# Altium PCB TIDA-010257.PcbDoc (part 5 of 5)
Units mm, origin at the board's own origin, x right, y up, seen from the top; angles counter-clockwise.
Board outline 250 x 270 mm, 2 copper layers (Top Layer, Bottom Layer), stack 1.575 mm thick; 458 components, 220 nets, 1154 pads, 1226 vias.
Unrouted connection lines stored in the file: 314.
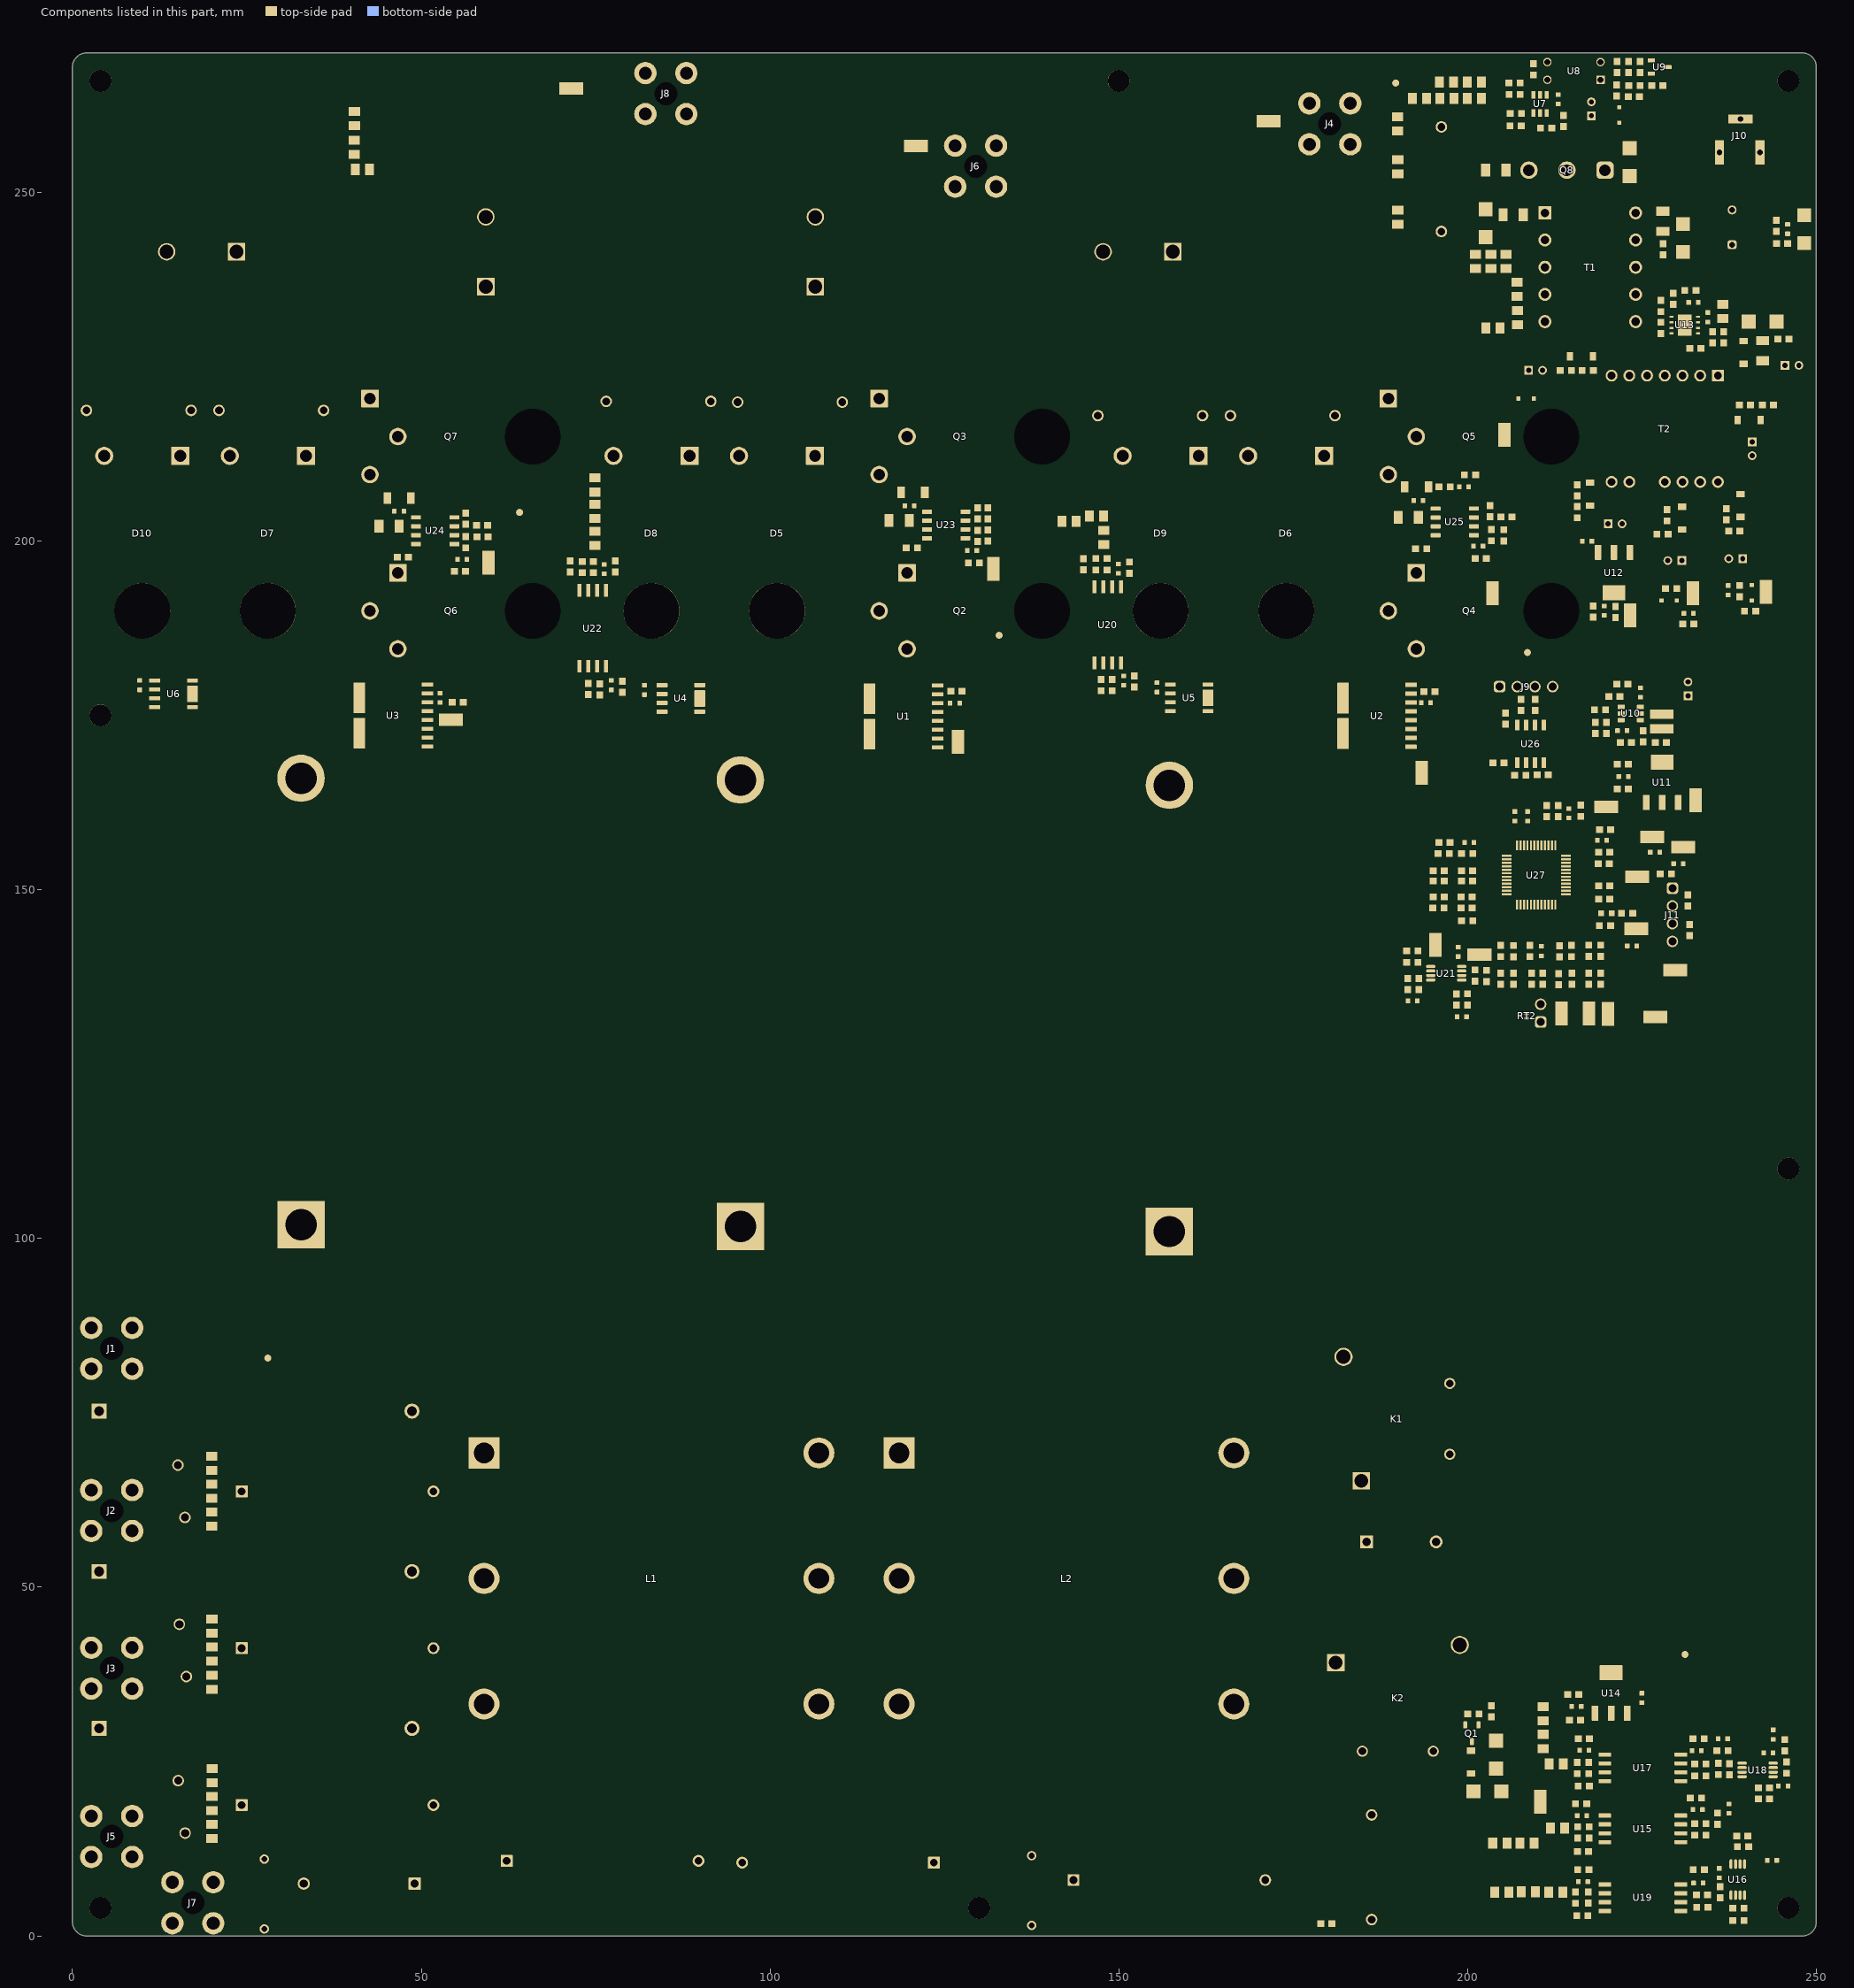
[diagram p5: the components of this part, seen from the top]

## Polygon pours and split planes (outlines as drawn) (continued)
VBUSM on Bottom Layer "BOTTOM_LAYER_VBUSM_P040" (solid, pour order 40): 70,197.842 70,192.467 71.46,191.007 77.247,191.007 77.815,191.575 77.815,193.77 78.75,194.705 78.75,198.826 77.55,200.026 70.737,200.026 70,199.289
GND_ISO on Bottom Layer "BOTTOM_LAYER_GND_ISO_P031" (solid, pour order 31): 202.929,180.586 202.929,173.956 204.069,172.816 212.251,172.816 213.75,174.315 213.75,180.314 212.974,181.09 203.433,181.09
VBUSN on Bottom Layer "BOTTOM_LAYER_VBUSN_P030" (solid, pour order 30): 199.682,34.584 199.353,34.584 192.442,34.584 188.118,30.26 182.885,30.26 182,29.375 182,20.5 183.345,19.155 190.45,19.155 204.833,19.155 205.949,20.271 205.949,33.142 204.831,34.26 204.318,34.26 203.968,34.584
GND_ACSensing on Bottom Layer "BOTTOM_LAYER_GND_ACSENSING_P024" (solid, pour order 24): 19 vertices, not listed, extent 191.25,0.5 227.336,38.883
GND_GATEC on Bottom Layer "Bottom Layer-GND_GATEC" (solid, pour order 6): 24 vertices, not listed, extent 40,182.25 51.145,220.148

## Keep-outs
Top Layer:
  circle w0.254: c4,4 r5
  circle w0.254: c246,4 r5
  circle w0.254: c4,175 r5
  circle w0.254: c246,110 r5
  circle w0.254: c246,266 r5
  circle w0.254: c4,266 r5
  circle w0.254: c150,266 r5
Bottom Layer:
  circle w0.254: c246,266 r3.553
  circle w0.254: c4,266 r3.553
  circle w0.254: c150,266 r3.553
Keep-Out Layer:
  circle w0.254: c246,110 r3.553
  text ".Layer_Name" at 14.656,-21.806 h1.52

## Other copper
Top Layer:
  text ".Layer_Name" at 14.656,-21.806 h1.52
Bottom Layer:
  text ".Layer_Name" at 14.656,-21.806 h1.52

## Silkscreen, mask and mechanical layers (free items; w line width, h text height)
Top Overlay:
  lines w0.2: 237.731,230.559 238.418,231.245 238.418,233.225 ; 203.211,106.245 203.211,107.612 210.177,107.612 210.177,108.612 211.877,106.912 210.177,105.212 210.177,106.245 203.211,106.245
  text "TIDA-010257" at 46.453,267.1 h1.5
  text "20241206" at 25.081,266.6 h1.5
  text "10kW Vienna PFC" at 42.748,264.68 h1.5
  text "VBUSN" at 90.979,264.44 h1.5
  text "VerB" at 27.5,264 h1.5
  text "GND" at 91.9,262 h1.5
  text "VBUSM" at 125.219,261.65 h1.5
  text "MID" at 127.066,259.621 h1.5
  text "VBUSP" at 167.738,256.78 h1.5
  text "Q5" at 193.507,216.906 h1
  text "Q7" at 48.725,214.45 h1
  text "Q3" at 121.98,214.45 h1
  text "15V_B" at 201.762,213.325 h1 r90
  text "D8" at 80.7,210.359 h1
  text "D9" at 153.95,209.756 h1
  text "D5" at 97.861,209.681 h1
  text "D7" at 24.7,209.516 h1
  text "D6" at 170.624,209.382 h1
  text "D10" at 6.706,209.2 h1
  text "PHASE B" at 171.076,202.907 h1.5
  text "PHASE C" at 26.55,202.183 h1.5
  text "PHASE A" at 98.161,201.812 h1.5
  text "PWMC" at 64.145,195.346 h1 r90
  text "PWMA" at 136.135,194.331 h1 r90
  text "PWMB" at 201.965,190.749 h1 r90
  text "15V_C" at 247.033,190.347 h1 r90
  text "15V_A" at 236.068,189.837 h1 r90
  text "Q6" at 39.117,189.467 h1
  text "Q2" at 111.82,189.379 h1
  text "Q4" at 185.026,189.24 h1
  text "3.3V_DC" at 225.846,184.237 h1 r90
  text "IC" at 56.614,173.817 h1
  text "IA" at 124.628,166.1 h1
  text "IB" at 192.425,161.602 h1
  text "5.4V" at 236.9,161.357 h1 r90
  text "3.3V" at 218.41,159.529 h1
  text "DAC0" at 228.378,159.19 h1
  text "DAC1" at 233.09,155.916 h1
  text "IO32" at 214.763,151.452 h1
  text "VP" at 191.069,145.192 h1
  text "VN" at 198.403,142.217 h1
  text "IO33" at 224.684,141.217 h1
  text "GND" at 232.538,138.528 h1
  text "GND" at 229.737,131.77 h1
  text "VB" at 218.477,127.974 h1 r90
  text "VC" at 222.462,127.906 h1 r90
  text "VA" at 214.944,127.774 h1 r90
  text "Soldering" at 200.5,103.7 h1.5
  text "A" at 2.5,90.9 h1.5
  text "10kW Vienna PFC" at 216.374,86.4 h1.5
  text "TIDA-010257" at 218.562,83.5 h1.5
  text "20241206" at 220.5,80.3 h1.5
  text "VerB" at 223.382,77.9 h1.5
  text "B" at 2.13,67.018 h1.5
  text "C" at 1.68,43.675 h1.5
  text "N" at 3.07,19.508 h1.5
  text "3.3V_AC" at 207.152,15.574 h1 r90
  text "E" at 10.2,1.3 h1.5
  text ".Layer_Name" at 14.656,-21.806 h1.52
Bottom Overlay:
  text ".Layer_Name" at 14.656,-21.806 h1.52
Top Paste:
  text ".Layer_Name" at 14.656,-21.806 h1.52
Bottom Paste:
  text ".Layer_Name" at 14.656,-21.806 h1.52
Top Solder:
  text ".Layer_Name" at 14.656,-21.806 h1.52
  text ".Layer_Name" at 14.656,-21.806 h1.52
Bottom Solder:
  lines w1: 72.3,79.1 72.3,82.4 ; 73.425,84.55 73.425,87.85 ; 74.3,79.1 74.3,82.4 ; 75.425,84.55 75.425,87.85 ; 76.3,79.1 76.3,82.4 ; 77.425,84.55 77.425,87.85 ; 78.3,79.1 78.3,82.4 ; 79.425,84.55 79.425,87.85 ; 80.3,79.1 80.3,82.4 ; 81.425,84.55 81.425,87.85 ; 82.3,79.1 82.3,82.4 ; 83.425,84.55 83.425,87.85 ; 84.3,79.1 84.3,82.4 ; 85.425,84.55 85.425,87.85 ; 86.3,79.1 86.3,82.4 ; 87.4,84.383 87.4,87.683 ; 87.425,84.55 87.425,87.85 ; 88.3,79.1 88.3,82.4 ; 89.425,84.55 89.425,87.85 ; 90.3,79.133 90.3,82.433 ; 91.425,84.583 91.425,87.883 ; 92.3,79.133 92.3,82.433 ; 92.325,79.3 92.325,82.6 ; 93.425,84.583 93.425,87.883 ; 94.3,79.133 94.3,82.433 ; 95.425,84.583 95.425,87.883 ; 96.3,79.133 96.3,82.433 ; 97.425,84.583 97.425,87.883 ; 98.3,79.133 98.3,82.433 ; 99.425,84.583 99.425,87.883 ; 100.3,79.133 100.3,82.433 ; 101.425,84.583 101.425,87.883 ; 102.3,79.133 102.3,82.433 ; 103.425,84.583 103.425,87.883 ; 104.3,79.133 104.3,82.433 ; 105.425,84.583 105.425,87.883 ; 106.3,79.133 106.3,82.433 ; 107.425,84.583 107.425,87.883 ; 108.3,79.133 108.3,82.433 ; 109.425,84.583 109.425,87.883 ; 110.3,79.133 110.3,82.433 ; 111.425,84.583 111.425,87.883 ; 112.3,79.133 112.3,82.433 ; 113.425,84.583 113.425,87.883 ; 114.3,79.133 114.3,82.433 ; 115.425,84.583 115.425,87.883 ; 116.3,79.133 116.3,82.433 ; 117.425,84.583 117.425,87.883 ; 118.3,79.133 118.3,82.433 ; 119.425,84.583 119.425,87.883 ; 120.4,79.133 120.4,82.433 ; 122.125,82.4 122.125,85.7 ; 123.1,76.95 123.1,80.25 ; 124.225,82.4 124.225,85.7 ; 125.1,76.95 125.1,80.25 ; 126.225,82.4 126.225,85.7 ; 127.1,76.95 127.1,80.25 ; 128.125,71.5 128.125,74.8 ; 128.225,82.4 128.225,85.7 ; 129.1,66.05 129.1,69.35 ; 129.1,76.95 129.1,80.25 ; 130.225,71.5 130.225,74.8 ; 131.1,66.05 131.1,69.35 ; 131.1,76.95 131.1,80.25 ; 132.225,71.5 132.225,74.8 ; 133.025,96.4 133.025,99.7 ; 133.1,66.05 133.1,69.35 ; 133.1,76.95 133.1,80.25 ; 134,90.95 134,94.25 ; 134.225,71.5 134.225,74.8 ; 135.1,66.05 135.1,69.35 ; 135.125,96.4 135.125,99.7 ; 135.3,75.85 135.3,79.15 ; 136,90.95 136,94.25 ; 136.225,71.5 136.225,74.8 ; 137.1,66.05 137.1,69.35 ; 137.125,96.4 137.125,99.7 ; 138,90.95 138,94.25 ; 138.225,71.5 138.225,74.8 ; 138.29,229.078 138.29,232.378 ; 138.8,86.25 138.8,89.55 ; 139.1,66.05 139.1,69.35 ; 139.125,96.4 139.125,99.7 ; 140,90.95 140,94.25 ; 140.39,229.061 140.39,232.361 ; 140.6,69.35 140.6,72.65 ; 140.9,86.233 140.9,89.533 ; 141.125,96.4 141.125,99.7 ; 141.567,224.95 141.567,228.25 ; 142,65.7 142,69 ; 142,90.95 142,94.25 ; 142.415,229.028 142.415,232.328 ; 142.925,86.2 142.925,89.5 ; 143.125,96.4 143.125,99.7 ; 143.567,224.95 143.567,228.25 ; 143.9,80.75 143.9,84.05 ; 144,90.95 144,94.25 ; 144.515,229.028 144.515,232.328 ; 145.025,86.2 145.025,89.5 ; 145.125,96.4 145.125,99.7 ; 145.567,224.95 145.567,228.25 ; 145.9,80.75 145.9,84.05 ; 146.515,229.028 146.515,232.328 ; 147.025,86.2 147.025,89.5 ; 147.567,224.95 147.567,228.25 ; 147.9,80.75 147.9,84.05 ; 148.515,229.028 148.515,232.328 ; 149.025,86.2 149.025,89.5 ; 149.567,224.95 149.567,228.25 ; 149.9,80.75 149.9,84.05 ; 150.515,229.028 150.515,232.328 ; 151.025,86.2 151.025,89.5 ; 151.567,224.95 151.567,228.25 ; 151.9,80.75 151.9,84.05 ; 152.515,229.028 152.515,232.328 ; 153.025,86.2 153.025,89.5 ; 153.9,80.75 153.9,84.05 ; 156.525,84.1 156.525,87.4 ; 157.5,78.65 157.5,81.95 ; 158.625,84.1 158.625,87.4 ; 159.5,78.65 159.5,81.95 ; 160.625,84.1 160.625,87.4 ; 161.5,78.65 161.5,81.95 ; 162.625,84.1 162.625,87.4 ; 163.5,78.65 163.5,81.95 ; 164.625,84.1 164.625,87.4 ; 165.5,78.65 165.5,81.95 ; 166.625,84.1 166.625,87.4 ; 167.5,78.65 167.5,81.95 ; 168.625,84.1 168.625,87.4 ; 169.6,78.65 169.6,81.95 ; 170.725,84.1 170.725,87.4 ; 171.6,78.65 171.6,81.95 ; 172.725,84.1 172.725,87.4 ; 173.6,78.65 173.6,81.95 ; 174.725,84.1 174.725,87.4 ; 175.6,78.65 175.6,81.95 ; 176.725,84.1 176.725,87.4 ; 177.6,78.65 177.6,81.95 ; 178.725,84.1 178.725,87.4 ; 179.6,78.65 179.6,81.95
  text ".Layer_Name" at 14.656,-21.806 h1.52
Drill Guide:
  text ".Layer_Name" at 14.656,-21.806 h1.52
M1 Board Outline:
  drawing of 167 lines, arcs and shapes, not listed
  text ".Layer_Name" at 14.656,-21.806 h1.52
M2 Board Dimensions:
  text ".Layer_Name" at 14.656,-21.806 h1.52
M3 3D STEP Top:
  text ".Layer_Name" at 14.656,-21.806 h1.52
M4 3D STEP Bottom:
  text ".Layer_Name" at 14.656,-21.806 h1.52
M5 Assembly Top:
  lines w0.254: -7.417,-23.626 160.223,-23.626 ; -7.417,-18.462 160.274,-18.462 ; -7.417,-13.297 -7.417,-28.791 94.31,-28.791 160.274,-28.791 160.274,-13.297 -7.404,-13.297 -7.404,-28.791 32.614,-28.791 ; 55.194,-28.791 55.194,-13.297 ; 87.376,-18.462 87.376,-13.297 ; 108.712,-18.462 108.712,-13.297 ; 124.511,-28.956 124.511,-23.804
  text "COMPONENTS MARKED 'DNP' SHOULD NOT BE POPULATED." at 29.299,-8.09 h1
  text "ASSEMBLY VARIANT:" at 29.286,-11.024 h1
  text ".VariantName" at 55.601,-11.024 h1
  text "PCB VIEWED FROM TOP SIDE" at -5.804,-16.654 h1.52
  text "BOARD #:" at 57.099,-16.654 h1.52
  text ".PRJ_Number" at 70.955,-16.654 h1.52
  text "REV:" at 92.405,-16.654 h1.52
  text ".PCB_Rev" at 99.809,-16.654 h1.52
  text "SVN REV:" at 113.69,-16.654 h1.52
  text ".VersionControl_RevNumber" at 126.543,-16.654 h1.52
  text "PLOT NAME =" at -5.804,-27.034 h1.52
  text ".plot_File_Name" at 14.656,-27.034 h1.52
  text "GENERATED    :" at 57.15,-27.034 h1.52
  text ".Print_Date" at 79.235,-27.034 h1.52
  text ".Print_Time" at 97.752,-27.034 h1.52
  text "TEXAS INSTRUMENTS" at 129.87,-27.034 h1.52
M6 Assembly Bottom:
  lines w0.254: -7.429,-18.474 160.261,-18.474 ; -7.379,-23.639 160.261,-23.639 ; 28.334,-28.969 28.334,-23.817 ; 44.133,-18.474 44.133,-13.31 ; 65.468,-18.474 65.468,-13.31 ; 97.65,-28.804 97.65,-13.31 ; 120.231,-28.804 160.249,-28.804 160.249,-13.31 -7.429,-13.31 -7.429,-28.804 58.534,-28.804 160.261,-28.804 160.261,-13.31
  text "COMPONENTS MARKED 'DNP' SHOULD NOT BE POPULATED." at 154.991,-8.077 h1
  text ".VariantName" at 128.473,-11.024 h1
  text "ASSEMBLY VARIANT:" at 154.864,-11.024 h1
  text ".VersionControl_RevNumber" at 26.302,-16.667 h1.52
  text "SVN REV:" at 39.154,-16.667 h1.52
  text ".PCB_Rev" at 53.035,-16.667 h1.52
  text "REV:" at 60.439,-16.667 h1.52
  text ".PRJ_Number" at 81.89,-16.667 h1.52
  text "BOARD #:" at 95.745,-16.667 h1.52
  text "PCB VIEWED FROM BOTTOM SIDE" at 158.648,-16.667 h1.52
  text "TEXAS INSTRUMENTS" at 22.974,-27.047 h1.52
  text ".Print_Time" at 55.093,-27.047 h1.52
  text ".Print_Date" at 73.609,-27.047 h1.52
  text "GENERATED    :" at 95.694,-27.047 h1.52
  text ".plot_File_Name" at 138.189,-27.047 h1.52
  text "PLOT NAME =" at 158.648,-27.047 h1.52
M9 Title Sheet:
  drawing of 63 lines, arcs and shapes, not listed
  text "1" at 35.293,466.75 h1.78
  text "2" at 136.766,466.75 h1.78
  text "3" at 238.239,466.75 h1.78
  text "4" at 339.865,466.75 h1.78
  text "5" at 441.423,466.75 h1.78
  text "6" at 542.98,466.75 h1.78
  text "7" at 644.623,466.75 h1.78
  text "8" at 746.096,466.75 h1.78
  text "A" at -11.874,405.841 h1.78
  text "A" at 793.305,405.841 h1.78
  text "B" at -11.874,278.841 h1.78
  text "B" at 793.305,278.841 h1.78
  text "C" at -11.874,151.841 h1.78
  text "C" at 793.305,151.841 h1.78
  text "D" at -11.874,24.841 h1.78
  text "D" at 793.305,24.841 h1.78
  text "PROJECT TITLE:" at 714.947,6.823 h1.14
  text ".PRJ_Title" at 716.216,3.436 h1.78
  text "DESIGNED FOR:" at 714.947,-0.823 h1.14
  text ".PRJ_Customer" at 716.216,-4.379 h1.78
  text "FILE NAME:" at 714.947,-8.443 h1.14
  text ".PCB_File_Name_No_Path" at 716.216,-11.491 h1.78
  text "Texas Instruments (TI) and/or its licensors do not warrant the accuracy or completeness of this specification" at 588.721,-15.601 h1.14
  text "ENGINEER:" at 714.947,-15.809 h1.14
  text "LAYOUT BY:" at 753.173,-15.809 h1.14
  text "or any information contained therein. TI and/or its licensors do not warrant that this design will meet" at 587.579,-18.463 h1.14
  text ".PRJ_Engineer" at 716.216,-19.746 h1.78
  text ".PCB_Layout" at 754.456,-19.746 h1.78
  text "the specifications, will be suitable for your application or fit for any particular purpose, or will operate in" at 587.579,-21.325 h1.14
  text ".Layer_Name" at 14.656,-21.806 h1.52
  text "ALTIUM DESIGNER VERSION:" at 753.173,-23.683 h1.14
  text "an implementation. TI and/or its licensors do not warrant that the design is production worthy. You should" at 587.579,-24.187 h1.14
  text "completely validate and test your design implementation to confirm the system functionality for your application." at 588.721,-27.048 h1.14
  text ".print_Scale" at 716.216,-27.069 h1.78
  text ".Application_BuildNumber" at 754.456,-27.069 h1.78
  text "1" at 35.293,-33.503 h1.78
  text "2" at 136.766,-33.503 h1.78
  text "3" at 238.239,-33.503 h1.78
  text "4" at 339.865,-33.503 h1.78
  text "5" at 441.423,-33.503 h1.78
  text "6" at 542.98,-33.503 h1.78
  text "7" at 644.623,-33.503 h1.78
  text "8" at 746.096,-33.503 h1.78
M10 Fab Notes:
  drawing of 380 lines, arcs and shapes, not listed
  text "DESIGN INFORMATION" at 741.376,161.675 h1.52
  text "MIN. TRACK WIDTH:" at 725.004,158.319 h1.52
  text "8" at 752.848,158.32 h1.52
  text "MIL" at 756.779,158.319 h1.52
  text "MIN. CLEARANCE:" at 725.004,155.167 h1.52
  text "7.874" at 748.5,155.167 h1.52
  text "MIL" at 756.779,155.167 h1.52
  text "MIN. VIA PAD SIZE:" at 725.004,152.014 h1.52
  text "24" at 752.087,152.014 h1.52
  text "MIL" at 756.779,152.014 h1.52
  text "0.05mm (2MIL)" at 742.657,148.714 h1.52
  text "MINIMUM ANNULAR RING" at 716.641,148.506 h1.52
  text "EXTERNAL" at 760.64,148.506 h1.52
  text "PER" at 721.721,145.708 h1.52
  text "IPC-D-275 CLASS 2 LEVEL C" at 727.309,145.708 h1.52
  text "Layer" at 261.353,144.454 h1.52
  text "Name" at 271.772,144.454 h1.52
  text "Material" at 295.402,144.454 h1.52
  text "Thickness" at 317.254,144.454 h1.52
  text "Constant" at 333.77,144.454 h1.52
  text "Board Layer Stack" at 348.254,144.454 h1.52
  text "MIL, HOLES" at 765.11,143.156 h1.52
  text "+/-" at 755.142,142.938 h1.52
  text "+/-" at 776.834,142.938 h1.52
  text "REGISTRATION TOLERANCES:" at 716.641,142.911 h1.52
  text "METAL" at 747.116,142.911 h1.52
  text "5" at 761.751,142.911 h1.52
  text "3" at 782.909,142.911 h1.52
  text "MIL" at 785.862,142.911 h1.52
  text "Top Overlay" at 271.772,141.404 h1.52
  text "HOLE SIZE TOLERANCE (UNLESS OTHERWISE SPECIFIED):" at 716.641,140.414 h1.52
  text "+/-" at 776.834,140.341 h1.52
  text "3" at 782.909,140.314 h1.52
  text "MIL" at 785.862,140.314 h1.52
  text "Top Solder" at 271.772,138.354 h1.52
  text "Solder Resist" at 295.402,138.354 h1.52
  text "0.010mm" at 317.254,138.354 h1.52
  text "3.5" at 333.77,138.354 h1.52
  text "MATERIAL:" at 714.742,136.818 h1.52
  text "1" at 261.353,135.304 h1.52
  text "Top Layer" at 271.772,135.304 h1.52
  text "0.036mm" at 317.254,135.304 h1.52
  text "FR-4 High Tg" at 739.798,133.553 h1.52
  text "X" at 736.129,133.35 h1.52
  text "FR-4" at 725.436,133.235 h1.52
  text "OTHER" at 763.231,133.235 h1.52
  text "Dielectric1" at 271.772,132.254 h1.52
  text "FR-4 High Tg" at 295.402,132.254 h1.52
  text "1.504mm" at 317.254,132.254 h1.52
  text "4.8" at 333.77,132.254 h1.52
  text "62 MIL (1.6mm) +/-10%" at 733.566,129.602 h1.52
  text "X" at 730.516,129.54 h1.52
  text "THICKNESS:" at 716.641,129.394 h1.52
  text "OTHER" at 766.203,129.394 h1.52
  text "2" at 261.353,129.204 h1.52
  text "Bottom Layer" at 271.772,129.204 h1.52
  text "0.036mm" at 317.254,129.204 h1.52
  text "Bottom Solder" at 271.772,126.154 h1.52
  text "Solder Resist" at 295.402,126.154 h1.52
  text "0.010mm" at 317.254,126.154 h1.52
  text "3.5" at 333.77,126.154 h1.52
  text "TOLERANCE:" at 716.641,125.88 h1.52
  text "X" at 738.187,125.88 h1.52
  text "ANSI IPC-6012 TYPE 3 CLASS 2" at 742.708,125.88 h1.52
  text "Bottom Overlay" at 271.772,123.104 h1.52
  text "OTHER +/-" at 742.708,122.218 h1.52
  text "Total board thickness:" at 261.353,120.054 h1.52
  text "1.595mm" at 317.254,120.054 h1.52
  text "BOW & TWIST:" at 716.641,118.53 h1.52
  text "X" at 738.187,118.53 h1.52
  text "ANSI IPC-6012 TYPE 3 CLASS 2" at 742.708,118.53 h1.52
  text "OTHER +/-" at 742.708,114.804 h1.52
  text "DRILLING:" at 714.742,111.486 h1.52
  text "NC_DRILL FILES" at 759.472,108.815 h1.52
  text "REFERENCE:" at 716.641,108.715 h1.52
  text "X" at 733.335,108.712 h1.52
  text "AS SHOWN" at 737.856,108.715 h1.52
  text "X" at 756.221,108.715 h1.52
  text "OTHER" at 767.041,105.101 h1.52
  text "PTH COPPER THICKNESS:" at 716.633,105.012 h1.52
  text "X" at 745.57,105.012 h1.52
  text "20-30 um" at 748.821,105.012 h1.52
  text "BOARD FINISH:" at 714.742,101.263 h1.52
  text "SILKSCREEN:" at 718.685,98.466 h1.52
  text "X" at 743.013,98.466 h1.52
  text "TOP" at 745.984,98.466 h1.52
  text "X" at 755.967,98.466 h1.52
  text "BOTTOM" at 758.964,98.466 h1.52
  text "SILKSCREEN COLOR:" at 718.685,94.524 h1.52
  text "X" at 742.987,94.524 h1.52
  text "WHITE" at 745.984,94.524 h1.52
  text "OTHER" at 758.964,94.524 h1.52
  text "X" at 746.315,90.88 h1.52
  text "GREEN" at 749.312,90.88 h1.52
  text "OTHER" at 765.009,90.88 h1.52
  text "SOLDER RESIST COLOR:" at 718.685,90.706 h1.52
  text "X" at 746.315,86.962 h1.52
  text "MATTE" at 749.312,86.962 h1.52
  text "SEMI-GLOSS" at 764.997,86.946 h1.52
  text "IMMERSION GOLD (ENIG)" at 741.692,82.574 h1.52
  text "ENEPIG" at 775.665,82.39 h1.52
  text "SURFACE FINISH:" at 714.742,82.365 h1.52
  text "X" at 737.171,82.365 h1.52
  text "IMM. TIN/SILVER OR EQUIV" at 723.113,78.877 h1.52
  text "OTHER" at 759.472,78.777 h1.52
  text "ARRAY/PANEL:" at 714.742,74.831 h1.52
  text "CUT AND TRIM PER M1 BOARD OUTLINE" at 741.692,74.622 h1.52
  text "N.C. ROUTE" at 741.692,71.168 h1.52
  text "X" at 759.167,71.168 h1.52
  text "V. SCORE" at 763.688,71.168 h1.52
  text "CERTIFICATION:" at 714.742,67.888 h1.52
  text "MATERIALS AND WORKMANSHIP FOR ALL PCBS" at 733.157,67.888 h1.52
  text "TO MEET OR EXCEED THE REQUIREMENTS OF:" at 733.157,65.499 h1.52
  text "X" at 723.95,62.232 h1.52
  text "ANSI IPC-A-600F CLASS ->" at 727.201,62.232 h1.52
  text "X" at 769.06,62.232 h1.52
  text "2" at 771.854,62.232 h1.52
  text "1" at 763.853,62.194 h1.52
  text "3" at 780.846,62.194 h1.52
  text "X" at 744.575,58.481 h1.52
  text "RoHS" at 747.826,58.481 h1.52
  text "OTHER" at 764.194,58.481 h1.52
  text "PER ORDER" at 774.279,58.481 h1.52
  text "ALL BOARDS MUST MEET OR EXCEED UL94-V0 REQUIREMENTS." at 715.442,54.574 h1.52
  text "PCB MUST BEAR THE UL94V-0 UL REGISTERED MATERIAL ID NUMBER" at 715.442,51.626 h1.52
  text "ADDITIONAL REQUIREMENTS:" at 714.742,47.322 h1.52
  text "MICROSECTION:" at 716.641,44.601 h1.52
  text "YES" at 739.647,44.601 h1.52
  text "REQUIRED" at 761.529,40.935 h1.52
  text "BARE BOARD ELEC. TEST:" at 716.641,40.863 h1.52
  text "NONE" at 749.807,40.863 h1.52
  text "X" at 758.532,40.863 h1.52
  text "PER ORDER" at 776.566,40.863 h1.52
  text "XX MIL VIAS REQUIRE NON-CONDUCTIVE FILL AND PLANARIZE" at 720.912,35.657 h1.5
  text "XX MIL VIAS REQUIRE CONDUCTIVE FILL AND PLANARIZE" at 721.116,33.016 h1.52
  text "OUTER XX MIL TRACES REQUIRE 50 OHM SINGLE-ENDED IMPEDANCE" at 721.091,28.866 h1.47
  text "LAYER 2 & 3 (INNER LAYERS) XX MIL WIDE, XX MIL SPACE / TRACES REQUIRE 100 OHM DIFFERENTIAL IMPEDANCE" at 720.887,22.879 h1.52
  text ".Layer_Name" at 14.656,-21.806 h1.52
M11 Gerber Information:
  lines w0.254: -7.417,-23.626 160.223,-23.626 ; -7.417,-18.462 160.274,-18.462 ; -7.417,-13.297 -7.417,-28.791 94.31,-28.791 160.274,-28.791 160.274,-13.297 -7.404,-13.297 -7.404,-28.791 32.614,-28.791 ; 55.194,-28.791 55.194,-13.297 ; 87.376,-18.462 87.376,-13.297 ; 108.712,-18.462 108.712,-13.297 ; 124.511,-28.956 124.511,-23.804
  text "ALL ARTWORK VIEWED FROM TOP SIDE" at -5.804,-16.654 h1.52
  text "BOARD #:" at 57.099,-16.654 h1.52
  text ".PRJ_Number" at 70.955,-16.654 h1.52
  text "REV:" at 92.405,-16.654 h1.52
  text ".PCB_Rev" at 99.809,-16.654 h1.52
  text "SVN REV:" at 113.69,-16.654 h1.52
  text ".VersionControl_RevNumber" at 126.543,-16.654 h1.52
  text "LAYER NAME =" at -5.804,-21.806 h1.52
  text "PLOT NAME =" at -5.804,-27.034 h1.52
  text ".plot_File_Name" at 14.656,-27.034 h1.52
  text "GENERATED    :" at 57.15,-27.034 h1.52
  text ".Print_Date" at 79.235,-27.034 h1.52
  text ".Print_Time" at 97.752,-27.034 h1.52
  text "TEXAS INSTRUMENTS" at 129.87,-27.034 h1.52
M12 Stackup:
  drawing of 191 lines, arcs and shapes, not listed
  text "Layer" at 673.945,458.309 h1
  text "Name" at 680.951,458.309 h1
  text "Material" at 696.621,458.309 h1
  text "Thickness" at 711.126,458.309 h1
  text "Constant" at 722.131,458.309 h1
  text "Board Layer Stack" at 731.803,458.309 h1
  text "Top Overlay" at 680.951,456.31 h1
  text "Top Solder" at 680.951,454.31 h1
  text "Solder Resist" at 696.621,454.31 h1
  text "0.40mil" at 711.126,454.31 h1
  text "3.5" at 722.131,454.31 h1
  text "1" at 673.945,452.31 h1
  text "Top Layer" at 680.951,452.31 h1
  text "1.40mil" at 711.126,452.31 h1
  text "Dielectric1" at 680.951,450.31 h1
  text "FR-4 High Tg" at 696.621,450.31 h1
  text "59.20mil" at 711.126,450.31 h1
  text "4.8" at 722.131,450.31 h1
  text "2" at 673.945,448.31 h1
  text "Bottom Layer" at 680.951,448.31 h1
  text "1.40mil" at 711.126,448.31 h1
  text "Bottom Solder" at 680.951,446.31 h1
  text "Solder Resist" at 696.621,446.31 h1
  text "0.40mil" at 711.126,446.31 h1
  text "3.5" at 722.131,446.31 h1
  text "Bottom Overlay" at 680.951,444.31 h1
  text ".Layer_Name" at 14.656,-21.806 h1.52
M13 Component Bodies Top:
  text ".Layer_Name" at 14.656,-21.806 h1.52
M14 Component Bodies Bottom:
  text ".Layer_Name" at 14.656,-21.806 h1.52
M15 Courtyards Top:
  text ".Layer_Name" at 14.656,-21.806 h1.52
M16 Courtyards Bottom:
  text ".Layer_Name" at 14.656,-21.806 h1.52
Drill Drawing:
  drawing of 186 lines, arcs and shapes, not listed
  text "Symbol" at 261.377,107.219 h1.83
  text "Count" at 274.226,107.219 h1.83
  text "Hole Size" at 290.731,107.219 h1.83
  text "Plated" at 319.933,107.219 h1.83
  text "Hole Type" at 332.782,107.219 h1.83
  text "Drill Layer Pair" at 351.421,107.219 h1.83
  text "Via/Pad" at 389.509,107.219 h1.83
  text "Pad Shape" at 404.491,107.219 h1.83
  text "Template" at 423.435,107.219 h1.83
  text "2" at 274.226,103.409 h1.52
  text "47.24mil (1.200mm)" at 290.731,103.409 h1.52
  text "PTH" at 319.933,103.409 h1.52
  text "Round" at 332.782,103.409 h1.52
  text "Top Layer - Bottom Layer" at 351.421,103.409 h1.52
  text "Pad" at 389.509,103.409 h1.52
  text "(Mixed)" at 404.491,103.409 h1.52
  text "(Mixed)" at 423.435,103.409 h1.52
  text "2" at 274.226,99.599 h1.52
  text "77.95mil (1.980mm)" at 290.731,99.599 h1.52
  text "PTH" at 319.933,99.599 h1.52
  text "Round" at 332.782,99.599 h1.52
  text "Top Layer - Bottom Layer" at 351.421,99.599 h1.52
  text "Pad" at 389.509,99.599 h1.52
  text "Rectangle" at 404.491,99.599 h1.52
  text "s250h198(Tol8-8)" at 423.435,99.599 h1.52
  text "2" at 274.226,95.789 h1.52
  text "81.10mil (2.060mm)" at 290.731,95.789 h1.52
  text "PTH" at 319.933,95.789 h1.52
  text "Round" at 332.782,95.789 h1.52
  text "Top Layer - Bottom Layer" at 351.421,95.789 h1.52
  text "Pad" at 389.509,95.789 h1.52
  text "Rounded" at 404.491,95.789 h1.52
  text "c260h206(Tol13-13)" at 423.435,95.789 h1.52
  text "3" at 274.226,91.979 h1.52
  text "31.50mil (0.800mm)" at 290.731,91.979 h1.52
  text "PTH" at 319.933,91.979 h1.52
  text "Slot" at 332.782,91.979 h1.52
  text "Top Layer - Bottom Layer" at 351.421,91.979 h1.52
  text "Pad" at 389.509,91.979 h1.52
  text "Rectangle" at 404.491,91.979 h1.52
  text "r350_130h80_300" at 423.435,91.979 h1.52
  text "4" at 274.226,88.169 h1.52
  text "42.91mil (1.090mm)" at 290.731,88.169 h1.52
  text "PTH" at 319.933,88.169 h1.52
  text "Round" at 332.782,88.169 h1.52
  text "Top Layer - Bottom Layer" at 351.421,88.169 h1.52
  text "Pad" at 389.509,88.169 h1.52
  text "Rounded" at 404.491,88.169 h1.52
  text "c160h109(Tol8-8)" at 423.435,88.169 h1.52
  text "6" at 274.226,84.359 h1.52
  text "55.12mil (1.400mm)" at 290.731,84.359 h1.52
  text "PTH" at 319.933,84.359 h1.52
  text "Round" at 332.782,84.359 h1.52
  text "Top Layer - Bottom Layer" at 351.421,84.359 h1.52
  text "Pad" at 389.509,84.359 h1.52
  text "(Mixed)" at 404.491,84.359 h1.52
  text "(Mixed)" at 423.435,84.359 h1.52
  text "6" at 274.226,80.549 h1.52
  text "177.17mil (4.500mm)" at 290.731,80.549 h1.52
  text "PTH" at 319.933,80.549 h1.52
  text "Round" at 332.782,80.549 h1.52
  text "Top Layer - Bottom Layer" at 351.421,80.549 h1.52
  text "Pad" at 389.509,80.549 h1.52
  text "(Mixed)" at 404.491,80.549 h1.52
  text "(Mixed)" at 423.435,80.549 h1.52
  text "8" at 274.226,76.739 h1.52
  text "78.74mil (2.000mm)" at 290.731,76.739 h1.52
  text "PTH" at 319.933,76.739 h1.52
  text "Round" at 332.782,76.739 h1.52
  text "Top Layer - Bottom Layer" at 351.421,76.739 h1.52
  text "Pad" at 389.509,76.739 h1.52
  text "(Mixed)" at 404.491,76.739 h1.52
  text "(Mixed)" at 423.435,76.739 h1.52
  text "8" at 274.226,72.929 h1.52
  text "124.02mil (3.150mm)" at 290.731,72.929 h1.52
  text "NPTH" at 319.933,72.929 h1.52
  text "Round" at 332.782,72.929 h1.52
  text "Top Layer - Bottom Layer" at 351.421,72.929 h1.52
  text "Pad" at 389.509,72.929 h1.52
  text "Rounded" at 404.491,72.929 h1.52
  text "c315hn315m315p-1" at 423.435,72.929 h1.52
  text "8" at 274.226,69.119 h1.52
  text "129.92mil (3.300mm)" at 290.731,69.119 h1.52
  text "NPTH" at 319.933,69.119 h1.52
  text "Round" at 332.782,69.119 h1.52
  text "Top Layer - Bottom Layer" at 351.421,69.119 h1.52
  text "Pad" at 389.509,69.119 h1.52
  text "Rounded" at 404.491,69.119 h1.52
  text "c300hn330m340" at 423.435,69.119 h1.52
  text "10" at 274.226,65.309 h1.52
  text "33.47mil (0.850mm)" at 290.731,65.309 h1.52
  text "PTH" at 319.933,65.309 h1.52
  text "Round" at 332.782,65.309 h1.52
  text "Top Layer - Bottom Layer" at 351.421,65.309 h1.52
  text "Pad" at 389.509,65.309 h1.52
  text "(Mixed)" at 404.491,65.309 h1.52
  text "(Mixed)" at 423.435,65.309 h1.52
  text "A" at 260.638,65.055 h1.69
  text "10" at 274.226,61.499 h1.52
  text "48.03mil (1.220mm)" at 290.731,61.499 h1.52
  text "PTH" at 319.933,61.499 h1.52
  text "Round" at 332.782,61.499 h1.52
  text "Top Layer - Bottom Layer" at 351.421,61.499 h1.52
  text "Pad" at 389.509,61.499 h1.52
  text "(Mixed)" at 404.491,61.499 h1.52
  text "(Mixed)" at 423.435,61.499 h1.52
  text "B" at 260.638,61.245 h1.69
  text "12" at 274.226,57.689 h1.52
  text "28.00mil (0.711mm)" at 290.731,57.689 h1.52
  text "PTH" at 319.933,57.689 h1.52
  text "Round" at 332.782,57.689 h1.52
  text "Top Layer - Bottom Layer" at 351.421,57.689 h1.52
  text "(Mixed)" at 389.509,57.689 h1.52
  text "(Mixed)" at 404.491,57.689 h1.52
  text "(Mixed)" at 423.435,57.689 h1.52
  text "C" at 260.638,57.435 h1.69
  text "12" at 274.226,53.879 h1.52
  text "66.93mil (1.700mm)" at 290.731,53.879 h1.52
  text "PTH" at 319.933,53.879 h1.52
  text "Round" at 332.782,53.879 h1.52
  text "Top Layer - Bottom Layer" at 351.421,53.879 h1.52
  text "Pad" at 389.509,53.879 h1.52
  text "(Mixed)" at 404.491,53.879 h1.52
  text "(Mixed)" at 423.435,53.879 h1.52
  text "E" at 260.638,53.625 h1.69
  text "12" at 274.226,50.069 h1.52
  text "116.14mil (2.950mm)" at 290.731,50.069 h1.52
  text "PTH" at 319.933,50.069 h1.52
  text "Round" at 332.782,50.069 h1.52
  text "Top Layer - Bottom Layer" at 351.421,50.069 h1.52
  text "Pad" at 389.509,50.069 h1.52
  text "(Mixed)" at 404.491,50.069 h1.52
  text "(Mixed)" at 423.435,50.069 h1.52
  text "12" at 274.226,46.259 h1.52
  text "314.96mil (8.000mm)" at 290.731,46.259 h1.52
  text "NPTH" at 319.933,46.259 h1.52
  text "Round" at 332.782,46.259 h1.52
  text "Top Layer - Bottom Layer" at 351.421,46.259 h1.52
  text "Pad" at 389.509,46.259 h1.52
  text "Rounded" at 404.491,46.259 h1.52
  text "(Mixed)" at 423.435,46.259 h1.52
  text "F" at 260.638,46.005 h1.69
  text "14" at 274.226,42.449 h1.52
  text "29.53mil (0.750mm)" at 290.731,42.449 h1.52
  text "PTH" at 319.933,42.449 h1.52
  text "Round" at 332.782,42.449 h1.52
  text "Top Layer - Bottom Layer" at 351.421,42.449 h1.52
  text "Pad" at 389.509,42.449 h1.52
  text "(Mixed)" at 404.491,42.449 h1.52
  text "(Mixed)" at 423.435,42.449 h1.52
  text "18" at 274.226,38.639 h1.52
  text "45.28mil (1.150mm)" at 290.731,38.639 h1.52
  text "PTH" at 319.933,38.639 h1.52
  text "Round" at 332.782,38.639 h1.52
  text "Top Layer - Bottom Layer" at 351.421,38.639 h1.52
  text "Pad" at 389.509,38.639 h1.52
  text "(Mixed)" at 404.491,38.639 h1.52
  text "(Mixed)" at 423.435,38.639 h1.52
  text "21" at 274.226,34.829 h1.52
  text "64.96mil (1.650mm)" at 290.731,34.829 h1.52
  text "PTH" at 319.933,34.829 h1.52
  text "Round" at 332.782,34.829 h1.52
  text "Top Layer - Bottom Layer" at 351.421,34.829 h1.52
  text "Pad" at 389.509,34.829 h1.52
  text "(Mixed)" at 404.491,34.829 h1.52
  text "(Mixed)" at 423.435,34.829 h1.52
  text "G" at 260.638,34.575 h1.69
  text "32" at 274.226,31.019 h1.52
  text "72.84mil (1.850mm)" at 290.731,31.019 h1.52
  text "PTH" at 319.933,31.019 h1.52
  text "Round" at 332.782,31.019 h1.52
  text "Top Layer - Bottom Layer" at 351.421,31.019 h1.52
  text "Pad" at 389.509,31.019 h1.52
  text "Rounded" at 404.491,31.019 h1.52
  text "c320h185" at 423.435,31.019 h1.52
  text "41" at 274.226,27.209 h1.52
  text "43.31mil (1.100mm)" at 290.731,27.209 h1.52
  text "PTH" at 319.933,27.209 h1.52
  text "Round" at 332.782,27.209 h1.52
  text "Top Layer - Bottom Layer" at 351.421,27.209 h1.52
  text "Pad" at 389.509,27.209 h1.52
  text "(Mixed)" at 404.491,27.209 h1.52
  text "(Mixed)" at 423.435,27.209 h1.52
  text "456" at 274.226,23.399 h1.52
  text "7.87mil (0.200mm)" at 290.731,23.399 h1.52
  text "PTH" at 319.933,23.399 h1.52
  text "Round" at 332.782,23.399 h1.52
  text "Top Layer - Bottom Layer" at 351.421,23.399 h1.52
  text "Via" at 389.509,23.399 h1.52
  text "Rounded" at 404.491,23.399 h1.52
  text "(Mixed)" at 423.435,23.399 h1.52
  text "D" at 260.638,23.145 h1.69
  text "760" at 274.226,19.589 h1.52
  text "23.62mil (0.600mm)" at 290.731,19.589 h1.52
  text "PTH" at 319.933,19.589 h1.52
  text "Round" at 332.782,19.589 h1.52
  text "Top Layer - Bottom Layer" at 351.421,19.589 h1.52
  text "Via" at 389.509,19.589 h1.52
  text "Rounded" at 404.491,19.589 h1.52
  text "v100h60" at 423.435,19.589 h1.52
  text "H" at 260.638,19.335 h1.69
  text "1459 Total" at 274.226,15.779 h1.52
  text "Slot definitions :" at 261.377,12.097 h1.52
  text "Routed Path Length" at 287.607,12.097 h1.52
  text "= Calculated from tool start centre position to tool end centre position." at 315.615,12.097 h1.52
  text "Hole Length" at 287.607,9.557 h1.52
  text "= Routed Path Length + Tool Size = Slot length as defined in the PCB layout" at 305.204,9.557 h1.52
  text ".Layer_Name" at 14.656,-21.806 h1.52
M17 Embedded Cavity:
  text ".Layer_Name" at 14.656,-21.806 h1.52
M18 Embedded Assembly:
  text ".Layer_Name" at 14.656,-21.806 h1.52
M19 Embedded Keepout:
  text ".Layer_Name" at 14.91,-21.552 h1.52

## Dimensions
211,206.5 to 246,266 on M2 Board Dimensions
214.5,203 to 246,266 on M2 Board Dimensions
130,4 to 246,4 on M2 Board Dimensions
4,4 to 130,4 on M2 Board Dimensions
246,110 to 246,266 on M2 Board Dimensions
246,4 to 246,110 on M2 Board Dimensions
4,175 to 4,266 on M2 Board Dimensions
4,4 to 4,175 on M2 Board Dimensions
246,266 to 150,266 on M2 Board Dimensions
4,266 to 150,266 on M2 Board Dimensions
248,2 to 243.1,-3.3 on M2 Board Dimensions
0,2 to 250,2 on M2 Board Dimensions
2,270 to 2,0 on M2 Board Dimensions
